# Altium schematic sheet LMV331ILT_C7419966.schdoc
size 127 x 101 mm
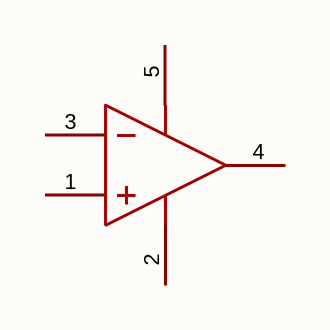
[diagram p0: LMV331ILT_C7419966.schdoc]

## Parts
U?  lmv331ilt_c7419966  [SOT-23-5_L3.0-W1.6-P0.95-LS2.8-BR]  (value not drawn)

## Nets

Not connected (* = marked no-connect by the designer): U? 1(+IN) 2(VCC-) 3(-IN) 4(OUT) 5(VCC+)

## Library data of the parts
U? = lmv331ilt_c7419966: Manufacturer: TECH PUBLIC(台舟); AddInBom: yes; ModelId: 72410e292833493f86746b22636ce101; ModelTransform: 110.236,116.1415,0,0,0,0,0.002,0.001,0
